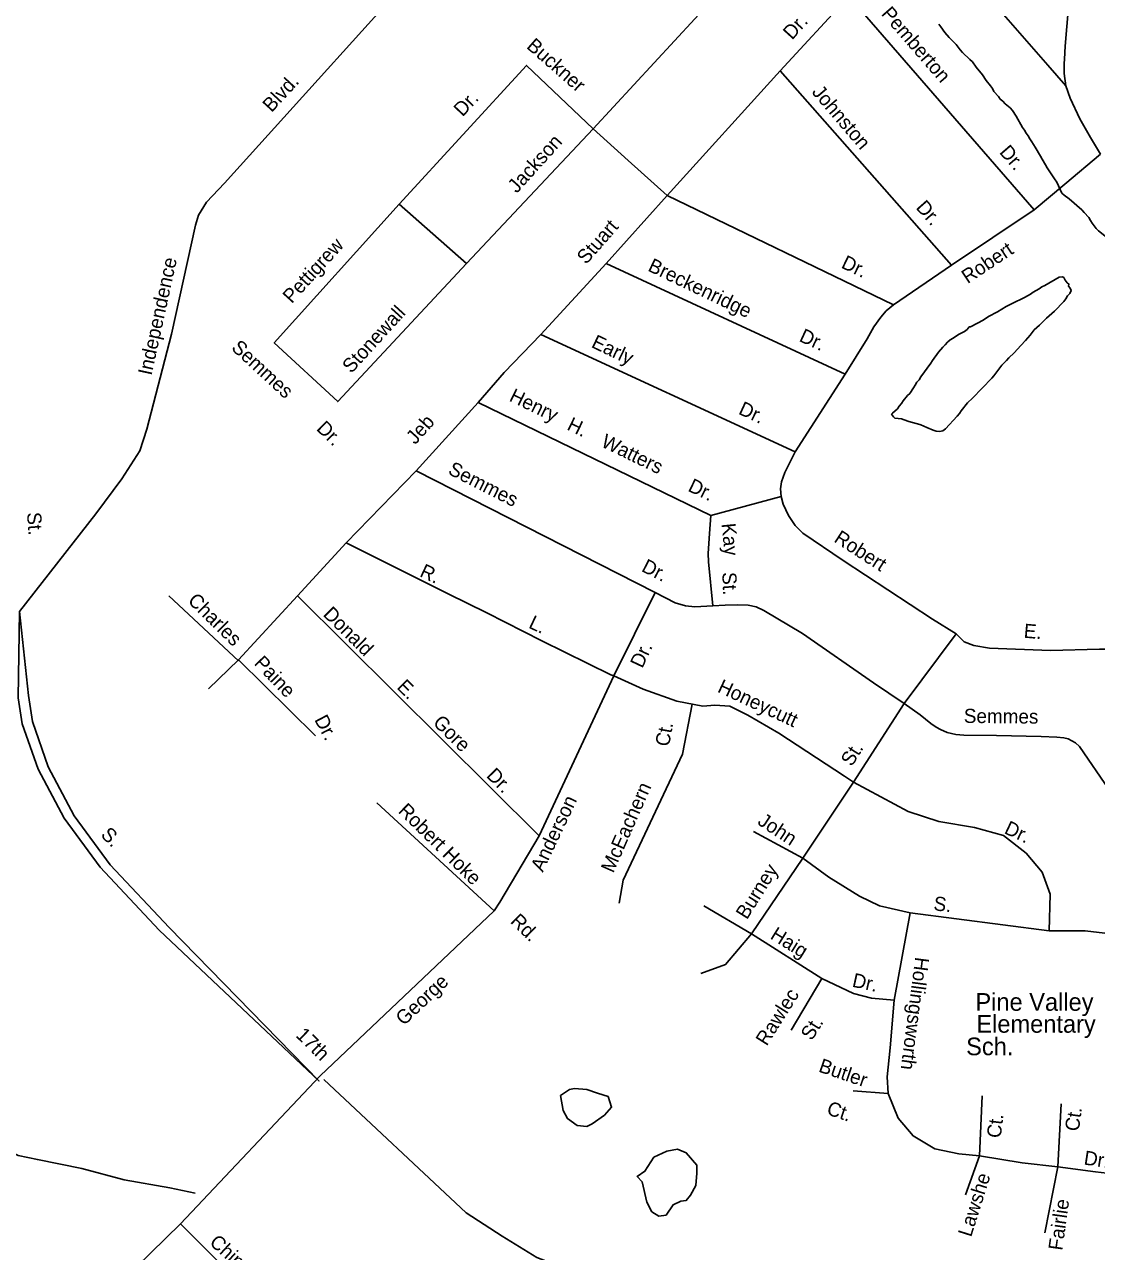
# Model space of a CAD drawing. Extents: x 1945482 to 2853149, y 66427 to 1015778.
# Drawn here: x 2327684 to 2332664, y 156815 to 162514 of the extents above; entities that cross this region are included whole.
import ezdxf

# ---------------------------------------------------------------- set-up
doc = ezdxf.new("R2010")
doc.units = 0
for name, color, linetype in [('Old_Level_10', 7, 'Continuous'), ('Old_Level_22', 7, 'Continuous'), ('Old_Level_35', 7, 'Continuous'), ('Old_Level_59', 7, 'Continuous'), ('Old_Level_60', 7, 'Continuous')]:
    doc.layers.add(name, color=color, linetype=linetype)

msp = doc.modelspace()

# ---------------------------------------------------------------- linework, layer by layer
at = {"layer": 'Old_Level_35'}
for p, q in [((2330325.7, 162030), (2331381, 163172.2)), ((2331513.7, 162645.4), (2331195.3, 162298.7)), ((2331513.7, 162645.4), (2332375.4, 161652.9)), ((2331195.3, 162298.7), (2330670.1, 161719.6)), ((2331991.4, 161395.8), (2331195.3, 162298.7)), ((2330325.7, 162030), (2329738.3, 161404.5)), ((2330489.3, 161882.5), (2330325.7, 162030)), ((2332518, 161772.5), (2332683.2, 161911.2)), ((2330670.1, 161719.6), (2330489.3, 161882.5)), ((2332375.4, 161652.9), (2332518, 161772.5)), ((2329425.1, 161680.2), (2329738.3, 161404.5)), ((2330386.5, 161404.2), (2330670.1, 161719.6)), ((2330670.1, 161719.6), (2331720.7, 161212.8)), ((2331991.4, 161395.8), (2332375.4, 161652.9)), ((2330083.5, 161074.2), (2330386.5, 161404.2)), ((2330386.5, 161404.2), (2331497.1, 160889.9)), ((2331720.7, 161212.8), (2331991.4, 161395.8)), ((2331265.3, 160528.9), (2330083.5, 161074.2)), ((2331265.3, 160528.9), (2331497.1, 160889.9)), ((2330873, 160233), (2329791.8, 160758.4)), ((2330873, 160233), (2331199.6, 160322.1)), ((2331771.6, 159360.1), (2332013.2, 159684.1)), ((2333195, 158232.3), (2332611.9, 158305.1))]:
    msp.add_line(p, q, dxfattribs=at)
for points in [[(2327661.6, 159787.7), (2328015.7, 160240.9), (2328136.2, 160403.3), (2328219.7, 160533.2), (2328252.1, 160635.2), (2328368, 161075.9), (2328479.3, 161582.1), (2328493.2, 161628.5), (2328530.3, 161688.8), (2328613.7, 161776.9), (2329642.9, 162918.1), (2329795.9, 163095.4), (2329860.8, 163216), (2329930.3, 163420.1), (2329953.5, 163666), (2329953.5, 163916.1)], [(2332585.5, 163219.8), (2332534.1, 162595.5), (2332519.3, 162413.1), (2332515.8, 162352.9), (2332514.6, 162332.8), (2332514.4, 162286.6), (2332522.6, 162229.1)], [(2332522.6, 162229.1), (2332438.4, 162325.2), (2331841.6, 163008.2)], [(2329425.1, 161680.2), (2330016, 162323.9), (2330325.7, 162030)], [(2332522.6, 162229.1), (2332542.9, 162171.8), (2332586.8, 162075.4), (2332636.1, 161989.4), (2332683.2, 161911.2)], [(2329738.3, 161404.5), (2329139.5, 160762.8), (2328844.5, 161035), (2329425.1, 161680.2)], [(2331497.1, 160889.9), (2331598.6, 161054), (2331630.6, 161109.4), (2331662.9, 161154.7), (2331687.7, 161183.6), (2331720.7, 161212.8)], [(2329791.8, 160758.4), (2329912.3, 160897.4), (2330083.5, 161074.2)], [(2329791.8, 160758.4), (2329504.3, 160441.1), (2330614.1, 159875.9)], [(2331199.6, 160322.1), (2331196.2, 160357.8), (2331200.9, 160390.1), (2331217.2, 160432.8), (2331265.3, 160528.9)], [(2329179.3, 160105.9), (2329504.3, 160441.1)], [(2331199.6, 160322.1), (2331208.9, 160286.4), (2331233, 160233.2), (2331265, 160186.5), (2331300.2, 160151.8), (2331487.4, 160025.3), (2331902.5, 159751.6), (2332013.2, 159684.1)], [(2330881.7, 159813.3), (2330861.4, 160018.6), (2330859.9, 160056.6), (2330866.4, 160150.7), (2330873, 160233)], [(2328952.1, 159860), (2329179.3, 160105.9)], [(2329179.3, 160105.9), (2329652.1, 159869.3), (2329832.9, 159781.2), (2330087.9, 159651.3), (2330407.8, 159493.5), (2330421.7, 159488.9)], [(2328678.6, 159558.5), (2328354.1, 159860)], [(2328678.6, 159563.1), (2328952.1, 159860)], [(2328952.1, 159860), (2330075.5, 158745.3)], [(2330421.7, 159488.9), (2330614.1, 159875.9)], [(2330614.1, 159875.9), (2330706.8, 159828.4), (2330755.6, 159814.2), (2330797.8, 159810), (2330881.7, 159813.3)], [(2330881.7, 159813.3), (2330939.3, 159817.5), (2330997.4, 159817.9), (2331045.6, 159817.8), (2331083.7, 159809.1), (2331118.5, 159792.5), (2331298.6, 159685.7), (2331628, 159456.5), (2331771.6, 159360.1)], [(2327661.6, 159787.7), (2327655.6, 159386.8), (2327674.2, 159266.1), (2327748.3, 159055.1), (2327868.9, 158827.7), (2328035.7, 158600.4), (2328309.3, 158308.2), (2329052.6, 157606.7), (2328356, 158319.4), (2328082.4, 158611.6), (2327915.6, 158839), (2327795, 159066.3), (2327720.8, 159277.4), (2327702.3, 159398), (2327661.6, 159787.7)], [(2332013.2, 159684.1), (2332050.4, 159647.5), (2332095.4, 159629.3), (2332167.8, 159618), (2332450.4, 159607.2), (2332678, 159612.3), (2332728.2, 159612.3), (2332779.1, 159588.4), (2332820.4, 159555.9), (2332877.6, 159478.1), (2333030, 159217.9), (2333106.1, 159111), (2333135.1, 159084.2), (2333162, 159067.2), (2333190.3, 159058.2), (2333299.2, 159034.6)], [(2328539.5, 159428.6), (2328678.6, 159563.1)], [(2329035.6, 159210.6), (2328678.6, 159563.1)], [(2330075.5, 158745.3), (2330421.7, 159488.9)], [(2330421.7, 159488.9), (2330558, 159426.7), (2330715.6, 159371.1), (2330836.1, 159347.9), (2330891.8, 159352.5), (2330961.3, 159347.9), (2331044.7, 159306.1), (2331188.5, 159222.6), (2331494.4, 159023.1), (2331536.1, 158995.3)], [(2330446.4, 158433.7), (2330464.9, 158539.8), (2330741.4, 159125.6), (2330786.6, 159357.4)], [(2331536.1, 158995.3), (2331771.6, 159360.1)], [(2331771.6, 159360.1), (2331845.9, 159307.3), (2331895.4, 159267.2), (2331920.1, 159250.2), (2331940.5, 159238.8), (2331971.2, 159226.3), (2332011.7, 159215.7), (2332047.6, 159213.2), (2332199.9, 159211.3), (2332408.2, 159207.4), (2332480.2, 159204.4), (2332512.4, 159201.4), (2332532.7, 159196.3), (2332567.2, 159177.6), (2332585.9, 159160.3), (2332626.3, 159101.9), (2332798.4, 158850.7)], [(2331536.1, 158995.3), (2331300.9, 158641.3), (2331061.3, 158290.8), (2330941.4, 158147.8), (2330826.2, 158106.3)], [(2332448.6, 158475.2), (2332411.7, 158576.7), (2332338, 158664.4), (2332232, 158747.4), (2332098.3, 158784.3), (2331932.4, 158811.9), (2331789.5, 158858.1), (2331536.1, 158995.3)], [(2329321.8, 158899.6), (2329865.7, 158396.8)], [(2330075.5, 158745.3), (2329893.3, 158438.3), (2329865.7, 158396.8), (2329057.4, 157631)], [(2331300.9, 158641.3), (2331070.5, 158765.8)], [(2331061.3, 158290.8), (2331388.5, 158083.2), (2331536, 158014), (2331619, 157991), (2331725, 157981.7), (2331798.7, 158387.6), (2331655.8, 158419.9), (2331563.6, 158466), (2331420.8, 158553.7), (2331300.9, 158641.3)], [(2331798.7, 158387.6), (2332444, 158304.6), (2332448.6, 158475.2)], [(2331061.3, 158290.8), (2330840, 158419.9)], [(2328476.6, 157085.3), (2328359.4, 157110.6), (2328147.9, 157148.2), (2327949.9, 157200.4), (2327744.1, 157242.1), (2327655.4, 157260.9), (2327618.5, 157279.5), (2327576.5, 157329.7), (2327542.5, 157384.5), (2327504, 157445), (2327427, 157524), (2327324.3, 157589.8), (2327077.4, 157758.3), (2326962.8, 157827.6), (2326861.7, 157901.7), (2326772.1, 157994), (2326694.1, 158089), (2326556.4, 158285.8)], [(2332444, 158304.6), (2332611.9, 158305.1)], [(2331388.5, 158083.2), (2331245.6, 157843.4)], [(2331725, 157981.7), (2331706.5, 157760.3), (2331692.7, 157626.6), (2331697.3, 157548.2), (2331743.4, 157434.7), (2331812.5, 157351.7), (2331913.9, 157291.7), (2332024.6, 157268.7), (2332121.3, 157259.5), (2332319.5, 157227.2), (2332485.5, 157208.7), (2332660.6, 157185.7), (2332817.3, 157167.2), (2333057, 157134.9), (2333112.3, 157559.3), (2333150.9, 157880.4)], [(2328409, 156943), (2329057.4, 157631)], [(2329074.5, 157614.2), (2329735.5, 156994.4), (2329904, 156887), (2330064.9, 156787.4), (2330306.6, 156694.5), (2332978.6, 156610), (2333405, 156611), (2333711.5, 156626.4), (2334109.8, 156703), (2334497.5, 156778.2), (2334742.6, 156808.8), (2335033.7, 156816.5), (2335352.2, 156786.3)], [(2331697.3, 157548.2), (2331534.3, 157561.7)], [(2332121.3, 157259.5), (2332133.3, 157538.7)], [(2332485.5, 157208.7), (2332501.1, 157500.3)], [(2332121.3, 157259.5), (2332056.7, 157078.7)], [(2332485.5, 157208.7), (2332424.5, 156902.4)], [(2327858.9, 156406.5), (2328409, 156943), (2328816.6, 156535.2), (2328956.6, 156414.2), (2329039.4, 156388.7), (2329205, 156318.6), (2329370.5, 156293.1), (2329497.9, 156274), (2329676.2, 156254.9), (2329886.3, 156203.9), (2330090.1, 156101.9), (2330306.6, 155980.8), (2330489.7, 155821.3)]]:
    msp.add_lwpolyline(points, dxfattribs=at)
at = {"layer": 'Old_Level_59'}
for points in [[(2332480.2, 161781.4), (2332470, 161797.9), (2332436, 161848.8), (2332428.2, 161862.7), (2332411.5, 161889.1), (2332404.5, 161903), (2332379.7, 161943.6), (2332363.5, 161969.8), (2332354.2, 161982.8), (2332347.5, 161996.7), (2332338.5, 162009.5), (2332330.5, 162023.2), (2332321.5, 162035.7), (2332290.7, 162089), (2332274, 162114.8), (2332264.2, 162126.6), (2332240.2, 162146), (2332230, 162157.3), (2332217.5, 162167.2), (2332208.5, 162179.7), (2332188, 162203.2), (2332181.5, 162217), (2332172.5, 162229.5), (2332152.2, 162253.5), (2332135.5, 162280.2), (2332106, 162315.5), (2332087.7, 162340.8), (2332076.5, 162352.2), (2332041.5, 162384.6), (2332030.7, 162395.8), (2332013, 162420.5), (2331980.2, 162453.9), (2331960, 162477.7), (2331941.5, 162502.9), (2331931.5, 162515)], [(2332816.2, 161478.5), (2332790.2, 161477.2), (2332753, 161493.1), (2332737.2, 161510.5), (2332724.5, 161519.4), (2332711, 161526.9), (2332673.7, 161555.5), (2332663, 161566.7), (2332644.5, 161590.9), (2332637.2, 161604.4), (2332628.7, 161617.6), (2332606.5, 161641.2), (2332596.7, 161653), (2332538.2, 161704.2), (2332514.2, 161721.3), (2332504, 161730.8), (2332480.2, 161781.4)]]:
    msp.add_lwpolyline(points, dxfattribs=at)
at = {"layer": 'Old_Level_60'}
for points in [[(2331935.5, 160623.5), (2331950.2, 160626.2), (2331963.2, 160635.7), (2332016.5, 160695.6), (2332027.5, 160706.9), (2332036.5, 160719.1), (2332065.5, 160756.8), (2332088.5, 160778.7), (2332133.2, 160825.7), (2332178, 160870.8), (2332188, 160882.2), (2332225.2, 160931.9), (2332247, 160954), (2332256.7, 160966.6), (2332281.5, 160988.9), (2332313.5, 161023.2), (2332334, 161046.6), (2332346, 161058.1), (2332356.7, 161070.6), (2332375.5, 161096), (2332386.7, 161106.8), (2332399.2, 161117.3), (2332432.5, 161150.6), (2332457, 161171.3), (2332469, 161182.9), (2332512, 161227.6), (2332522, 161240), (2332530, 161253.3), (2332540, 161265.1), (2332546.2, 161279.1), (2332542.2, 161289.6), (2332535, 161298.4), (2332536.2, 161308.5), (2332528.5, 161314), (2332519, 161326), (2332512, 161339.4), (2332506.5, 161342.1), (2332491.7, 161340.4), (2332424.2, 161302.4), (2332410, 161295.3), (2332397.5, 161286.7), (2332370.7, 161271.1), (2332358, 161262), (2332330.2, 161245.8), (2332273.5, 161217.8), (2332244.7, 161204.6), (2332204, 161179.4), (2332162.7, 161157.3), (2332137.5, 161140.5), (2332082.5, 161111.9), (2332078.5, 161110), (2332073.5, 161109.8), (2332063.7, 161097.6), (2332051.5, 161088.2), (2332023.2, 161074.9), (2331998, 161056.7), (2331984.5, 161048.8), (2331972.5, 161038.1), (2331962.2, 161026.6), (2331950.2, 161016), (2331930, 160991.7), (2331903, 160954.2), (2331895, 160941), (2331848.5, 160877.4), (2331840.5, 160863.8), (2331830, 160852.6), (2331822.5, 160838.4), (2331813.7, 160826.2), (2331797.7, 160800.3), (2331786.2, 160790.3), (2331766.5, 160766.9), (2331758.5, 160753.3), (2331748.5, 160741.5), (2331740, 160729.1), (2331716.7, 160708.8), (2331712.7, 160704.3), (2331720.7, 160691.5), (2331728, 160685.1), (2331743.2, 160684.8), (2331759, 160682.2), (2331788.5, 160671), (2331803.2, 160666.4), (2331833.7, 160659.2), (2331848.2, 160654.4), (2331862, 160648.7), (2331876.2, 160641.7), (2331905, 160629.8), (2331919.5, 160625.3), (2331935.5, 160623.5)], [(2330174.7, 157538.9), (2330215.6, 157567.5), (2330240.1, 157571.6), (2330297.2, 157567.5), (2330346.2, 157551.2), (2330395.2, 157534.8), (2330411.5, 157485.8), (2330378.9, 157449), (2330321.7, 157408.1), (2330297.2, 157395.9), (2330252.3, 157400), (2330207.4, 157432.7), (2330187, 157469.4), (2330174.7, 157538.9)], [(2330607.5, 157252.9), (2330566.7, 157187.5), (2330529.9, 157163), (2330554.4, 157138.4), (2330574.8, 157044.4), (2330599.3, 156999.5), (2330632, 156979.1), (2330664.7, 156983.1), (2330697.3, 157032.2), (2330734.1, 157048.5), (2330758.6, 157052.6), (2330779, 157077.1), (2330803.5, 157122.1), (2330807.6, 157179.3), (2330807.6, 157216.1), (2330758.6, 157273.3), (2330717.7, 157289.6), (2330668.7, 157281.5), (2330607.5, 157252.9)]]:
    msp.add_lwpolyline(points, dxfattribs=at)

# ---------------------------------------------------------------- texts
at = {"layer": 'Old_Level_10'}
for s, height, rotation, p in [('Pemberton', 65.62, 310.9657, (2331661.4, 162562.1)), ('Dr.', 65.62, 47.7246, (2331250.2, 162439.5)), ('Buckner', 65.62, 318.757, (2330012.6, 162407.5)), ('Blvd.', 65.62, 47.3981, (2328832.3, 162102.6)), ('Johnston', 65.62, 310.4672, (2331338.9, 162198.6)), ('Dr.', 65.62, 46.9313, (2329719.4, 162082.6)), ('Jackson', 65.62, 47.9408, (2329971.1, 161727.2)), ('Dr.', 65.62, 310.9657, (2332210.2, 161919.1)), ('Dr.', 65.62, 311.4057, (2331822.2, 161662.1)), ('Stuart', 65.62, 48.7583, (2330293.3, 161396.2)), ('Pettigrew', 65.62, 47.7621, (2328926, 161214.8)), ('Robert', 65.62, 33.6034, (2332065.4, 161308)), ('Independence', 65.617, 77.6615, (2328274.3, 160881.3)), ('Breckenridge', 65.617, 334.4439, (2330576, 161372)), ('Dr.', 65.62, 334.2452, (2331474.2, 161386.3)), ('Stonewall', 65.62, 47.7053, (2329202.6, 160890.1)), ('Early', 65.62, 334.4343, (2330313.4, 161017)), ('Dr.', 65.62, 335.1512, (2331278.9, 161045.1)), ('Semmes', 65.62, 317.2984, (2328641.2, 161007.3)), ('Henry', 65.62, 334.0854, (2329931.9, 160767.8)), ('Dr.', 65.62, 335.2291, (2330997.1, 160706.8)), ('Dr.', 65.62, 315.6793, (2329036.8, 160633.3)), ('Jeb', 65.62, 48.0649, (2329499.3, 160559.8)), ('H.', 65.62, 334.0854, (2330200.3, 160634.4)), ('Watters', 65.62, 334.0854, (2330358.4, 160556.1)), ('Semmes', 65.62, 333.0064, (2329647.4, 160428.8)), ('Dr.', 65.62, 334.0854, (2330762.3, 160349.5)), ('St.', 65.62, 274.3275, (2327695.5, 160246.5)), ('Kay', 65.62, 275.6364, (2330922.3, 160195)), ('Robert', 65.62, 327.1675, (2331440.6, 160114.1)), ('Dr.', 65.62, 333.0064, (2330546.5, 159976.6)), ('R.', 65.62, 334.8004, (2329516, 159952.5)), ('St.', 65.62, 272.2687, (2330925.8, 159969.4)), ('Charles', 65.62, 315.4393, (2328439, 159833.8)), ('Donald', 65.62, 315.3708, (2329067.7, 159770.6)), ('L.', 65.62, 334.8623, (2330022, 159713.6)), ('E.', 65.62, 355.1231, (2332324.8, 159666.1)), ('Dr.', 65.62, 64.8034, (2330554.3, 159520.5)), ('Paine', 65.62, 313.5663, (2328747.2, 159544.4)), ('E.', 65.62, 315.3708, (2329410.2, 159432.5)), ('Honeycutt', 65.62, 334.9546, (2330899.5, 159416)), ('Dr.', 65.62, 297.7838, (2329029.4, 159285.7)), ('Gore', 65.62, 315.3708, (2329577.9, 159266.9)), ('Semmes', 65.62, 359.364, (2332048, 159270.4)), ('Ct.', 65.62, 79.7318, (2330678.2, 159157.4)), ('St.', 65.62, 57.9157, (2331527.6, 159064.2)), ('Dr.', 65.62, 314.5535, (2329826.6, 159022.2)), ('McEachern', 65.62, 66.2624, (2330419.5, 158569.5)), ('Robert Hoke', 65.617, 315.4416, (2329416.5, 158857.1)), ('Anderson', 65.62, 64.5638, (2330091.9, 158573.9)), ('John', 65.62, 326.6382, (2331085.5, 158801.9)), ('S.', 65.62, 314.6146, (2328034.6, 158747.2)), ('Dr.', 65.62, 334.6914, (2332231.5, 158759.2)), ('Burney', 65.62, 57.9157, (2331040.2, 158353.2)), ('S.', 65.62, 352.8888, (2331904.9, 158400.5)), ('Rd.', 65.62, 315.6773, (2329937.5, 158344.5)), ('Haig', 65.62, 328.1529, (2331144.3, 158270.7)), ('Hollingsworth', 65.617, 262.578, (2331822.9, 158185.1)), ('George', 65.62, 43.2642, (2329446.4, 157860.9)), ('Dr.', 65.62, 347.6672, (2331526, 158045.4)), ('Rawlec', 65.62, 57.7777, (2331132.2, 157766.2)), ('St.', 65.62, 57.7777, (2331341.6, 157790.8)), ('17th', 65.62, 315.3435, (2328940.9, 157815.8)), ('Butler', 65.62, 341.1905, (2331369.5, 157651.3)), ('Ct.', 65.62, 341.1905, (2331406.8, 157453.5)), ('Ct.', 65.62, 82.097, (2332582.1, 157370.7)), ('Ct.', 65.62, 83.1482, (2332219.3, 157339.4)), ('Dr.', 65.62, 351.3831, (2332602.9, 157219.4)), ('Lawshe', 65.62, 72.4593, (2332081.8, 156879.1)), ('Fairlie', 65.62, 82.0691, (2332505.3, 156817.3)), ('Chippenham', 65.62, 317.6176, (2328539.3, 156851.8))]:
    msp.add_text(s, height=height, rotation=rotation, dxfattribs=at).set_placement(p)
at = {"layer": 'Old_Level_22'}
for s, height, p in [('Pine Valley', 82.021, (2332102, 157933)), ('Elementary', 82.02, (2332106.4, 157831.1)), ('Sch.', 82.02, (2332059, 157726.6))]:
    msp.add_text(s, height=height, dxfattribs=at).set_placement(p)

doc.saveas('drawing.dxf')
